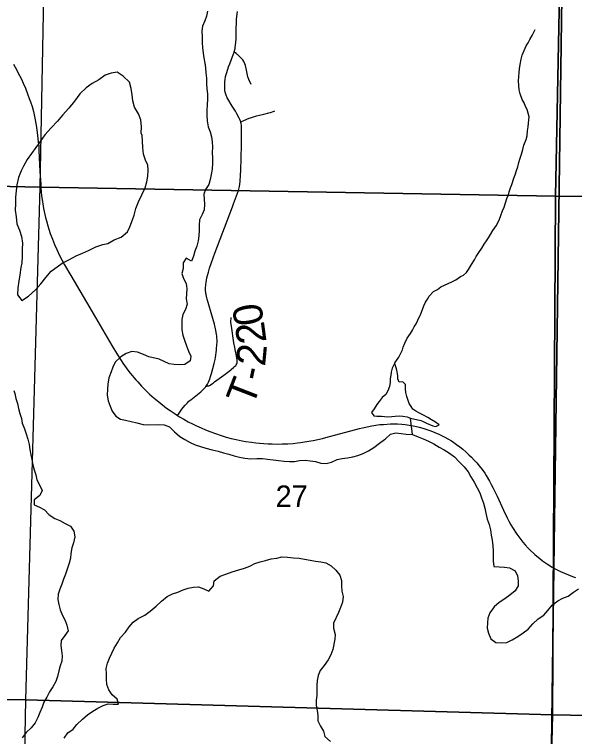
# Model space of a CAD drawing. Extents: x 0 to 34, y 0 to 22.
# Drawn here: x 19.172 to 20.261, y 16.628 to 18.033 of the extents above; entities that cross this region are included whole.
import ezdxf

# ---------------------------------------------------------------- set-up
doc = ezdxf.new("R2010")
doc.units = 0
for name, color, linetype in [('GM_X_Corporation', 7, 'Continuous'), ('GM_X_Major_Lake', 7, 'Continuous'), ('GM_X_Minor_River', 7, 'Continuous'), ('GM_X_Section_Text', 7, 'Continuous'), ('GM_X_Township_Road', 7, 'Continuous'), ('GM_X_Township_Road_Text', 7, 'Continuous'), ('GM_X_US_Route', 7, 'Continuous')]:
    doc.layers.add(name, color=color, linetype=linetype)

msp = doc.modelspace()

# ---------------------------------------------------------------- linework, layer by layer
at = {"layer": 'GM_X_Corporation'}
for points in [[(18.6, 19.2331), (18.6, 14.6606), (18.9216, 14.6592), (19.4007, 14.6554), (19.8855, 14.6528), (20.2016, 14.6512), (20.203, 14.81), (20.1987, 15.2691), (20.2208, 16.9558), (20.2471, 18.8539), (20.254, 19.2058), (20.065, 19.208), (18.9898, 19.2261)], [(18.6, 18.7129), (18.6, 17.7098), (19.222, 17.6968), (19.241, 18.7106)], [(19.241, 18.7106), (20.2437, 18.6978), (20.2237, 17.6792), (19.222, 17.6968)], [(21.2582, 18.6819), (21.2422, 17.6682), (20.2237, 17.6792), (20.2437, 18.6978)], [(18.6, 17.7098), (18.6, 16.7037), (19.1937, 16.6992), (19.222, 17.6968)], [(20.2237, 17.6792), (20.2179, 16.6698), (19.1937, 16.6992), (19.222, 17.6968)], [(21.2422, 17.6682), (21.2309, 16.6512), (20.2179, 16.6698), (20.2237, 17.6792)], [(18.6, 16.7037), (18.6, 15.673), (19.1743, 15.6658), (19.1937, 16.6992)], [(19.1937, 16.6992), (20.2179, 16.6698), (20.1931, 15.6647), (19.1743, 15.6658)], [(20.2179, 16.6698), (21.2309, 16.6512), (21.2159, 15.6439), (20.1931, 15.6647)]]:
    msp.add_lwpolyline(points, close=True, dxfattribs=at)
msp.add_lwpolyline([(25.4, 14.4307), (25.4, 19.0068), (24.5766, 19.0222), (24.3186, 19.0261), (24.3186, 19.1409), (24.169, 19.1418), (23.786, 19.1434), (23.5499, 19.1465), (23.3329, 19.1508), (22.6423, 19.1645), (21.8956, 19.1793), (21.7744, 19.1817), (21.5297, 19.1865), (21.2652, 19.1913), (20.8916, 19.1966), (20.254, 19.2058), (20.2471, 18.8539), (20.2208, 16.9558), (20.1987, 15.2691)], dxfattribs=at)
at = {"layer": 'GM_X_Major_Lake'}
for points in [[(19.5473, 18.0389), (19.5451, 18.0295), (19.542, 18.02), (19.5375, 18.0097), (19.536, 17.9999), (19.5368, 17.9892), (19.5368, 17.9775), (19.5372, 17.968), (19.5387, 17.9574), (19.5402, 17.9479), (19.5421, 17.938), (19.5432, 17.9285), (19.544, 17.9191), (19.5452, 17.9084), (19.5452, 17.8978), (19.5459, 17.8876), (19.5471, 17.8781), (19.5471, 17.8675), (19.5463, 17.8565), (19.5456, 17.8466), (19.5456, 17.8364), (19.5467, 17.8257), (19.5486, 17.814), (19.552, 17.8041), (19.5547, 17.7943), (19.5562, 17.7844), (19.5566, 17.7742), (19.5562, 17.7639), (19.5566, 17.7529), (19.5566, 17.7431), (19.5563, 17.7313), (19.5544, 17.721), (19.5525, 17.7112), (19.5498, 17.7017), (19.5434, 17.6922), (19.54, 17.6827), (19.5404, 17.6729), (19.5415, 17.6634), (19.5408, 17.6527), (19.5366, 17.6433), (19.5317, 17.633), (19.5306, 17.6224), (19.531, 17.6129), (19.5299, 17.6019), (19.5287, 17.592), (19.5265, 17.5818), (19.5223, 17.5719), (19.5197, 17.5624), (19.5159, 17.5526), (19.5057, 17.5586), (19.5, 17.5491)], [(19.4202, 17.7971), (19.4182, 17.8016), (19.4189, 17.8141), (19.4172, 17.8274), (19.413, 17.8391), (19.4049, 17.8519), (19.4017, 17.8644), (19.4009, 17.8761), (19.3988, 17.8886), (19.3953, 17.9011), (19.3834, 17.9124), (19.3712, 17.9202), (19.3595, 17.9182), (19.3482, 17.9147), (19.3358, 17.9051), (19.323, 17.8985), (19.3109, 17.89), (19.2985, 17.8778), (19.2885, 17.8636), (19.2772, 17.8503), (19.2649, 17.8369), (19.2555, 17.8246), (19.2431, 17.812), (19.2308, 17.7982), (19.2218, 17.7856), (19.1964, 17.7505)], [(19.1964, 17.7505), (19.1893, 17.7375), (19.1848, 17.728), (19.1797, 17.7151), (19.176, 17.701), (19.175, 17.6896), (19.174, 17.6771), (19.1737, 17.6638), (19.1731, 17.6517), (19.1747, 17.6388), (19.1764, 17.6251), (19.1814, 17.6127), (19.1857, 17.6002), (19.1874, 17.5877), (19.1867, 17.5752), (19.1865, 17.5615), (19.1858, 17.5494), (19.184, 17.5399), (19.1819, 17.5258), (19.1801, 17.5137), (19.1784, 17.5004), (19.1777, 17.4871), (19.1858, 17.4762), (19.199, 17.4847), (19.2125, 17.4966), (19.223, 17.5084), (19.2327, 17.521), (19.2432, 17.5333), (19.2549, 17.5417), (19.2646, 17.5483), (19.2775, 17.5552), (19.2914, 17.5629), (19.3038, 17.5684), (19.3159, 17.5734), (19.3299, 17.5804), (19.3435, 17.5851), (19.3533, 17.5867), (19.3653, 17.594), (19.3789, 17.5994), (19.3913, 17.6094), (19.3962, 17.6193), (19.4013, 17.6327), (19.4043, 17.6422), (19.4076, 17.6551), (19.4127, 17.668), (19.4194, 17.6814), (19.4257, 17.6951), (19.429, 17.7069), (19.4308, 17.7179), (19.4315, 17.7293), (19.431, 17.7395), (19.4263, 17.7493), (19.4228, 17.761), (19.4216, 17.7735), (19.4207, 17.7861), (19.4202, 17.7971)], [(19.5, 17.5491), (19.5, 17.5385), (19.4974, 17.5283), (19.5004, 17.5188), (19.5057, 17.5093), (19.5072, 17.4987), (19.5057, 17.479), (19.5076, 17.4687), (19.5046, 17.4585), (19.4993, 17.449), (19.497, 17.4387), (19.4974, 17.4289), (19.4971, 17.4186), (19.499, 17.4084), (19.5024, 17.3989), (19.5062, 17.3875), (19.5103, 17.3773), (19.5145, 17.3678), (19.5134, 17.3583), (19.5032, 17.3515), (19.4929, 17.3507), (19.4823, 17.3515), (19.4725, 17.353), (19.4626, 17.3571), (19.4528, 17.3617), (19.4331, 17.3662), (19.4225, 17.3711), (19.4108, 17.3757), (19.3998, 17.3768), (19.3892, 17.373), (19.3786, 17.3662), (19.3676, 17.3563), (19.3627, 17.3464), (19.3597, 17.3369), (19.3555, 17.3255), (19.3533, 17.313), (19.3529, 17.3032), (19.3522, 17.2918), (19.3537, 17.2808), (19.3575, 17.2701), (19.3616, 17.2607), (19.3685, 17.2508), (19.3779, 17.2448), (19.3878, 17.2432), (19.3988, 17.2406), (19.4094, 17.238), (19.4219, 17.2346), (19.4321, 17.2338), (19.4525, 17.2346), (19.4627, 17.2338), (19.473, 17.2304), (19.4828, 17.2202), (19.493, 17.2115), (19.5029, 17.2058), (19.5131, 17.1997), (19.5229, 17.1952), (19.5332, 17.1918), (19.5438, 17.1884), (19.5559, 17.1854), (19.5676, 17.1827), (19.5782, 17.1797), (19.5888, 17.1767), (19.5987, 17.174), (19.6096, 17.171), (19.6199, 17.1691), (19.6316, 17.168), (19.643, 17.1684), (19.6539, 17.1684), (19.6638, 17.1673), (19.6748, 17.1658), (19.685, 17.1646), (19.6963, 17.1631), (19.7066, 17.1624), (19.7164, 17.1624), (19.7262, 17.1647), (19.7368, 17.1654), (19.7467, 17.1643), (19.7573, 17.1624), (19.7675, 17.1594), (19.7781, 17.1587), (19.7883, 17.1617), (19.7993, 17.1666), (19.8091, 17.1685), (19.819, 17.1697), (19.8296, 17.1716), (19.8394, 17.1746), (19.8496, 17.1785), (19.8602, 17.1834), (19.8705, 17.1899), (19.8814, 17.1986), (19.8913, 17.2058), (19.8932, 17.2069)], [(19.1703, 17.3009), (19.1724, 17.295), (19.1746, 17.2855), (19.1777, 17.2756), (19.1796, 17.2658), (19.1822, 17.2559), (19.1853, 17.2464), (19.1868, 17.237), (19.1909, 17.226), (19.1944, 17.2165), (19.1978, 17.2059), (19.2004, 17.1956), (19.2019, 17.1858), (19.2038, 17.1759), (19.2054, 17.1664), (19.2076, 17.1565), (19.2103, 17.1463), (19.213, 17.1368), (19.2152, 17.127), (19.2205, 17.1171), (19.2255, 17.1061), (19.2209, 17.0966), (19.21, 17.0879), (19.2103, 17.0784), (19.2206, 17.0739), (19.2304, 17.0689), (19.2395, 17.0587), (19.2501, 17.0519), (19.26, 17.0477), (19.2702, 17.042), (19.2804, 17.0367), (19.2872, 17.0269), (19.2891, 17.0159), (19.2865, 17.0045), (19.2831, 16.995), (19.2816, 16.984), (19.2804, 16.9745), (19.2778, 16.965), (19.2748, 16.9552), (19.271, 16.9434), (19.2668, 16.9335), (19.2638, 16.924), (19.26, 16.9142), (19.257, 16.9047), (19.2559, 16.894), (19.2578, 16.8842), (19.2604, 16.8743), (19.2654, 16.8629), (19.2703, 16.8535), (19.2733, 16.844), (19.276, 16.8334), (19.2699, 16.8239), (19.2627, 16.8144), (19.262, 16.8045), (19.2631, 16.795), (19.2643, 16.7844), (19.2635, 16.7745), (19.2605, 16.765), (19.2579, 16.7556), (19.2552, 16.7442), (19.2522, 16.7347), (19.2465, 16.724), (19.2397, 16.7146), (19.2344, 16.7043), (19.2291, 16.6944), (19.2253, 16.6849), (19.2208, 16.6743), (19.217, 16.6648), (19.2117, 16.6542), (19.2042, 16.6447), (19.1947, 16.6352), (19.1868, 16.6249)], [(19.8932, 17.2069), (19.903, 17.2157), (19.9132, 17.2183), (19.9234, 17.2172), (19.9337, 17.2157), (19.9454, 17.215), (19.9564, 17.2108), (19.9666, 17.207), (19.9768, 17.2021), (19.9874, 17.1968), (19.9976, 17.1904), (20.0075, 17.1854), (20.0177, 17.1786), (20.0276, 17.1718), (20.0367, 17.1619), (20.0461, 17.1521), (20.0537, 17.1426), (20.059, 17.1328), (20.0658, 17.1225), (20.0715, 17.1115), (20.0764, 17.102), (20.0802, 17.0922), (20.0836, 17.0816), (20.0863, 17.0717), (20.0886, 17.0622), (20.0912, 17.0508), (20.0947, 17.0402), (20.0973, 17.0296), (20.0985, 17.0194), (20.1004, 17.0099), (20.1019, 16.9985), (20.1026, 16.989), (20.1026, 16.9693), (20.1038, 16.9587), (20.114, 16.9575), (20.1246, 16.9568), (20.1345, 16.956), (20.1451, 16.95), (20.15, 16.9401), (20.1515, 16.9306), (20.1515, 16.9208), (20.1455, 16.9109), (20.1349, 16.9025), (20.125, 16.8957), (20.1144, 16.8881), (20.1046, 16.8801), (20.0959, 16.868), (20.0921, 16.8581), (20.0914, 16.8486), (20.091, 16.8384), (20.0933, 16.8289), (20.0982, 16.8179), (20.108, 16.8103), (20.1186, 16.81), (20.1292, 16.8107), (20.1398, 16.816), (20.1504, 16.8221), (20.1607, 16.8293), (20.1705, 16.8366), (20.1796, 16.8468), (20.1902, 16.8563), (20.2008, 16.8635), (20.2087, 16.873), (20.2174, 16.8829), (20.2284, 16.8913), (20.2382, 16.897), (20.2484, 16.9008), (20.2587, 16.9087), (20.2685, 16.9152)], [(19.2856, 16.6417), (19.2931, 16.6512), (19.3037, 16.6615), (19.3135, 16.6699), (19.3238, 16.6767), (19.3336, 16.6828), (19.3442, 16.6877), (19.354, 16.6915), (19.3639, 16.6908), (19.3741, 16.6908), (19.3711, 16.7003), (19.3616, 16.7086), (19.3555, 16.7181), (19.3514, 16.7287), (19.3506, 16.739), (19.3506, 16.7496), (19.3502, 16.7602), (19.3525, 16.7705), (19.3563, 16.7799), (19.3608, 16.7898), (19.3657, 16.7993), (19.3721, 16.8099), (19.3782, 16.8202), (19.3873, 16.8308), (19.3948, 16.8407), (19.4024, 16.8502), (19.4122, 16.8574), (19.4251, 16.8639), (19.4357, 16.8715), (19.4471, 16.8813), (19.4573, 16.8908), (19.4686, 16.9003), (19.4788, 16.9053), (19.4891, 16.9083), (19.4997, 16.9129), (19.5095, 16.9163), (19.5197, 16.9182), (19.5296, 16.9186), (19.5398, 16.9148), (19.5496, 16.9107), (19.5587, 16.9209), (19.5598, 16.9304), (19.5716, 16.9399), (19.5825, 16.9437), (19.595, 16.9479), (19.6083, 16.9521), (19.6192, 16.9551), (19.6291, 16.9589), (19.6393, 16.9643), (19.6495, 16.9673), (19.6601, 16.9704), (19.6707, 16.9734), (19.6817, 16.9749), (19.6915, 16.9772), (19.7025, 16.9765), (19.7146, 16.9753), (19.7256, 16.9746), (19.7358, 16.9727), (19.7468, 16.9708), (19.7574, 16.9689), (19.7673, 16.9674), (19.7771, 16.9655), (19.7873, 16.9595), (19.7968, 16.9511), (19.8047, 16.9413), (19.8078, 16.9314), (19.8074, 16.9208), (19.8085, 16.9102), (19.8108, 16.8999), (19.8093, 16.8893), (19.8055, 16.8787), (19.8021, 16.8692), (19.7923, 16.8479), (19.7923, 16.8381), (19.7953, 16.8263), (19.7946, 16.8168), (19.7908, 16.7971), (19.787, 16.7865), (19.7817, 16.777), (19.7742, 16.766), (19.7659, 16.7561), (19.7621, 16.7462), (19.7606, 16.7364), (19.7598, 16.7269), (19.7598, 16.7075), (19.7583, 16.698), (19.7583, 16.6885), (19.7602, 16.6783), (19.7617, 16.6684), (19.7617, 16.6578), (19.7667, 16.6479), (19.7727, 16.6381), (19.7754, 16.6278), (19.786, 16.6176)], [(19.2681, 16.6243), (19.2757, 16.6345), (19.2856, 16.6417)]]:
    msp.add_lwpolyline(points, dxfattribs=at)
at = {"layer": 'GM_X_Minor_River'}
for p, q in [((19.942, 17.2471), (19.9618, 17.2426)), ((19.9454, 17.215), (19.942, 17.2471))]:
    msp.add_line(p, q, dxfattribs=at)
for points in [[(19.9113, 17.3547), (19.9147, 17.3593), (19.9194, 17.3655), (19.9227, 17.3735), (19.9264, 17.3797), (19.9278, 17.3854), (19.9311, 17.3931), (19.9355, 17.4027), (19.9415, 17.4119), (19.9455, 17.4184), (19.9492, 17.4249), (19.9526, 17.4307), (19.9562, 17.438), (19.9621, 17.4503), (19.965, 17.4587), (19.9676, 17.4656), (19.9709, 17.4725), (19.975, 17.4786), (19.9783, 17.4844), (19.9865, 17.4932), (19.994, 17.4972), (20.0011, 17.5026), (20.0079, 17.5057), (20.015, 17.5093), (20.0225, 17.5124), (20.0297, 17.5163), (20.0391, 17.5226), (20.0447, 17.5253), (20.0507, 17.5304), (20.0544, 17.5361), (20.0607, 17.5461), (20.0662, 17.5553), (20.0695, 17.5615), (20.0747, 17.5692), (20.0807, 17.578), (20.0851, 17.5857), (20.0895, 17.5922), (20.0936, 17.598), (20.0973, 17.6045), (20.1017, 17.6122), (20.1084, 17.6214), (20.1117, 17.6272), (20.115, 17.6341), (20.1176, 17.6414), (20.1205, 17.6502), (20.1238, 17.6578), (20.1267, 17.6662), (20.1292, 17.6746), (20.1321, 17.6815), (20.134, 17.6877), (20.1361, 17.6949), (20.139, 17.7018), (20.143, 17.7137), (20.1456, 17.7206), (20.1477, 17.729), (20.1503, 17.7362), (20.1524, 17.7443), (20.1542, 17.7508), (20.1575, 17.7607), (20.16, 17.7699), (20.1625, 17.7783), (20.1665, 17.7894), (20.1687, 17.7966), (20.1693, 17.8062), (20.1707, 17.8142), (20.1714, 17.821), (20.172, 17.8275), (20.1723, 17.8336), (20.1684, 17.8473), (20.1656, 17.8537), (20.1629, 17.8609), (20.159, 17.8673), (20.155, 17.8783), (20.1534, 17.8859), (20.1525, 17.8946), (20.1516, 17.903), (20.1523, 17.9117), (20.1529, 17.9197), (20.1539, 17.927), (20.1553, 17.9354), (20.1567, 17.9457), (20.1592, 17.9533), (20.1629, 17.9625), (20.1669, 17.9713), (20.1706, 17.9771), (20.1736, 17.984), (20.1787, 17.9917), (20.1842, 18.0035)], [(19.9618, 17.2426), (19.9651, 17.2413), (19.9728, 17.2373), (19.985, 17.2321), (19.9914, 17.2307), (19.9974, 17.2338), (19.9902, 17.239), (19.9829, 17.2435), (19.9756, 17.2483), (19.9661, 17.2535), (19.9596, 17.2565), (19.9524, 17.2609), (19.9466, 17.2643), (19.9428, 17.2699), (19.9393, 17.2756), (19.9365, 17.2832), (19.9345, 17.2892), (19.9329, 17.2972), (19.9324, 17.304), (19.9319, 17.3124), (19.9266, 17.318), (19.9201, 17.3172), (19.917, 17.3236), (19.9169, 17.3297), (19.9161, 17.3373), (19.9145, 17.343), (19.9129, 17.349), (19.9113, 17.3547), (19.9061, 17.344), (19.904, 17.3363), (19.9033, 17.3306), (19.9022, 17.3234), (19.902, 17.3169), (19.9009, 17.3085), (19.8977, 17.3005), (19.8936, 17.2932), (19.8869, 17.287), (19.8809, 17.2797), (19.8765, 17.2735), (19.8709, 17.265), (19.8661, 17.2581), (19.8704, 17.2513), (19.8764, 17.251), (19.8851, 17.2508), (19.8912, 17.2501), (19.898, 17.2498), (19.9056, 17.2503), (19.912, 17.2508), (19.9196, 17.2513), (19.9271, 17.251), (19.9351, 17.2496), (19.942, 17.2471)]]:
    msp.add_lwpolyline(points, dxfattribs=at)
at = {"layer": 'GM_X_Township_Road'}
for points in [[(19.4889, 17.2524), (19.4917, 17.257), (19.4971, 17.2647), (19.4999, 17.2681), (19.5036, 17.2724), (19.508, 17.2771), (19.5109, 17.2799), (19.5144, 17.2828), (19.5274, 17.2931), (19.5338, 17.2982), (19.5361, 17.3003), (19.5429, 17.3074), (19.5441, 17.3088), (19.5456, 17.311), (19.5469, 17.3132), (19.5489, 17.3173), (19.5514, 17.3234), (19.5538, 17.3301), (19.555, 17.3341), (19.5599, 17.3533), (19.5617, 17.3612), (19.5625, 17.3652), (19.5645, 17.3791), (19.5648, 17.3829), (19.5656, 17.3953), (19.565, 17.4071), (19.5648, 17.4096), (19.5633, 17.4183), (19.5627, 17.4209), (19.5606, 17.4297), (19.5572, 17.441), (19.5462, 17.4783), (19.5455, 17.4813), (19.5442, 17.4878), (19.5438, 17.4897), (19.5435, 17.4965), (19.5434, 17.4994), (19.5438, 17.5069), (19.5443, 17.5109), (19.5458, 17.5198), (19.5471, 17.5247), (19.5488, 17.5313), (19.5511, 17.5391), (19.5582, 17.5592), (19.5615, 17.5678), (19.5956, 17.6581), (19.5979, 17.6638), (19.6072, 17.6902), (19.608, 17.6929), (19.6091, 17.6975), (19.6099, 17.7023), (19.6105, 17.7077), (19.6113, 17.7208), (19.6116, 17.7291), (19.6133, 17.7783), (19.6134, 17.7857), (19.6135, 17.8063), (19.6133, 17.8133), (19.6132, 17.8163), (19.6124, 17.8205), (19.612, 17.8221), (19.6116, 17.8234), (19.6099, 17.8279), (19.6086, 17.8308), (19.604, 17.8393), (19.6014, 17.8441), (19.595, 17.8544), (19.5866, 17.8681), (19.5856, 17.8702), (19.5835, 17.8756), (19.5827, 17.8776), (19.5817, 17.8815), (19.581, 17.8849), (19.5806, 17.8879), (19.5808, 17.9022), (19.5812, 17.9054), (19.5823, 17.9118), (19.5831, 17.9154), (19.5844, 17.9198), (19.5879, 17.9306), (19.5904, 17.9362), (19.5979, 17.9559), (19.5983, 17.9571), (19.5989, 17.9596), (19.6006, 17.9661), (19.6011, 17.9684), (19.6018, 17.9731), (19.6023, 17.9786), (19.6027, 17.9845), (19.6031, 18.0018), (19.6033, 18.0192), (19.6036, 18.0232), (19.6056, 18.0381)], [(19.6317, 17.8964), (19.6277, 17.9058), (19.6256, 17.9115), (19.6248, 17.9144), (19.6224, 17.9275), (19.621, 17.9335), (19.6186, 17.9398), (19.6178, 17.9413), (19.6157, 17.9441), (19.6145, 17.9456), (19.6088, 17.9517), (19.6056, 17.9545), (19.6044, 17.9555), (19.6025, 17.9568), (19.5989, 17.9596)], [(19.6116, 17.8234), (19.6175, 17.8261), (19.628, 17.8306), (19.6305, 17.8315), (19.6424, 17.8351), (19.6485, 17.8367), (19.6569, 17.8387), (19.6661, 17.841), (19.6693, 17.8419), (19.6768, 17.8443), (19.6781, 17.8448)], [(19.5441, 17.3088), (19.548, 17.3097), (19.5494, 17.3102), (19.5508, 17.3109), (19.5578, 17.3154), (19.5608, 17.3175), (19.5791, 17.331), (19.5891, 17.3387), (19.5976, 17.3454), (19.5998, 17.3473), (19.6019, 17.3493), (19.6031, 17.351), (19.6039, 17.3526), (19.6045, 17.3544), (19.6047, 17.3556), (19.6049, 17.3586), (19.6048, 17.3599), (19.6032, 17.3682), (19.6013, 17.3776), (19.6001, 17.3843), (19.5985, 17.3938), (19.5935, 17.4259), (19.593, 17.4294), (19.5926, 17.4338), (19.5931, 17.4427)]]:
    msp.add_lwpolyline(points, dxfattribs=at)
at = {"layer": 'GM_X_US_Route'}
for points in [[(19.1697, 17.9359), (19.1731, 17.9299), (19.1818, 17.9136), (19.1853, 17.9065), (19.1888, 17.8988), (19.1929, 17.8891), (19.1971, 17.8782), (19.2005, 17.8687), (19.2027, 17.8626), (19.2059, 17.8537), (19.2086, 17.844), (19.2119, 17.8275), (19.2144, 17.813), (19.2164, 17.7969), (19.218, 17.7848), (19.2189, 17.7764), (19.2193, 17.768), (19.2212, 17.7267), (19.2227, 17.7018), (19.2232, 17.6948), (19.2245, 17.6798), (19.2253, 17.6728), (19.2276, 17.6597), (19.2284, 17.655), (19.2323, 17.6375), (19.2337, 17.6313), (19.2367, 17.6214), (19.2386, 17.6149), (19.2414, 17.6064), (19.2457, 17.5953), (19.2494, 17.5852), (19.254, 17.5751), (19.2596, 17.5634), (19.2639, 17.5548), (19.2692, 17.5452), (19.281, 17.5248), (19.329, 17.443), (19.3609, 17.3886), (19.3721, 17.37), (19.379, 17.3592), (19.3823, 17.3539), (19.3924, 17.3401), (19.3969, 17.3345), (19.4075, 17.3218), (19.4113, 17.3175), (19.4188, 17.3095), (19.4271, 17.301), (19.4344, 17.2939), (19.4434, 17.286), (19.449, 17.2813), (19.4633, 17.2698), (19.4675, 17.2667), (19.4745, 17.2618), (19.484, 17.2555), (19.4889, 17.2524), (19.4929, 17.2499), (19.501, 17.245), (19.5098, 17.2401), (19.5179, 17.2359), (19.5255, 17.2321), (19.5348, 17.2279), (19.5429, 17.2244), (19.5519, 17.2208), (19.5627, 17.217), (19.5738, 17.2133), (19.5836, 17.2103), (19.5934, 17.2076), (19.6031, 17.2054), (19.6143, 17.203), (19.6216, 17.2017), (19.6325, 17.2001), (19.6411, 17.199), (19.6485, 17.1983), (19.6651, 17.1972), (19.6728, 17.1968), (19.6827, 17.1966), (19.6925, 17.1968), (19.7036, 17.1973), (19.7139, 17.198), (19.722, 17.1988), (19.7279, 17.1996), (19.7478, 17.2027), (19.7526, 17.2036), (19.7705, 17.2076), (19.7773, 17.2093), (19.8428, 17.2269), (19.8487, 17.2283), (19.8578, 17.2304), (19.8669, 17.2321), (19.8744, 17.2334), (19.8821, 17.2344), (19.8892, 17.235), (19.9027, 17.2357), (19.9095, 17.2359), (19.9163, 17.2357), (19.9247, 17.2352), (19.9312, 17.2345), (19.9389, 17.2334), (19.947, 17.232), (19.9532, 17.2307), (19.9589, 17.2293), (19.9659, 17.2274), (19.9733, 17.2251), (19.9812, 17.2223), (19.9894, 17.2191), (19.9966, 17.216), (20.002, 17.2134), (20.0084, 17.2102), (20.0146, 17.2068), (20.0215, 17.2027), (20.0258, 17.1999), (20.0315, 17.196), (20.0378, 17.1913), (20.0438, 17.1866), (20.0497, 17.1814), (20.0555, 17.1759), (20.0607, 17.171), (20.0658, 17.1656), (20.0708, 17.1599), (20.0753, 17.1545), (20.081, 17.1471), (20.0862, 17.1397), (20.089, 17.1352), (20.0952, 17.1245), (20.0987, 17.118), (20.1027, 17.1106), (20.1103, 17.095), (20.1229, 17.0679), (20.1297, 17.0531), (20.1332, 17.0464), (20.1369, 17.0397), (20.1402, 17.0341), (20.1484, 17.0214), (20.1523, 17.016), (20.1604, 17.0057), (20.1647, 17.0005), (20.1706, 16.9942), (20.1732, 16.9916), (20.1837, 16.9816), (20.1872, 16.9785), (20.1931, 16.9737), (20.1988, 16.9693), (20.2042, 16.9654), (20.2083, 16.9627)], [(20.2083, 16.9627), (20.2174, 16.9572), (20.2218, 16.9547), (20.2272, 16.9518), (20.2335, 16.9486), (20.2412, 16.9452), (20.2488, 16.942), (20.2571, 16.9389), (20.2627, 16.937)]]:
    msp.add_lwpolyline(points, dxfattribs=at)

# ---------------------------------------------------------------- texts
at = {"layer": 'GM_X_Section_Text'}
msp.add_text('27', height=0.04186, rotation=0, dxfattribs=at).set_placement((19.6796, 17.0742))
at = {"layer": 'GM_X_Township_Road_Text'}
for s, rotation, p in [('0', 99.03, (19.6572, 17.432)), ('2', 97.4482, (19.662, 17.3956)), ('2', 84.4944, (19.6589, 17.3468)), ('-', 78.3362, (19.6532, 17.3173)), ('T', 68.7708, (19.6349, 17.2678))]:
    msp.add_text(s, height=0.0568, rotation=rotation, dxfattribs=at).set_placement(p)

doc.saveas('drawing.dxf')
